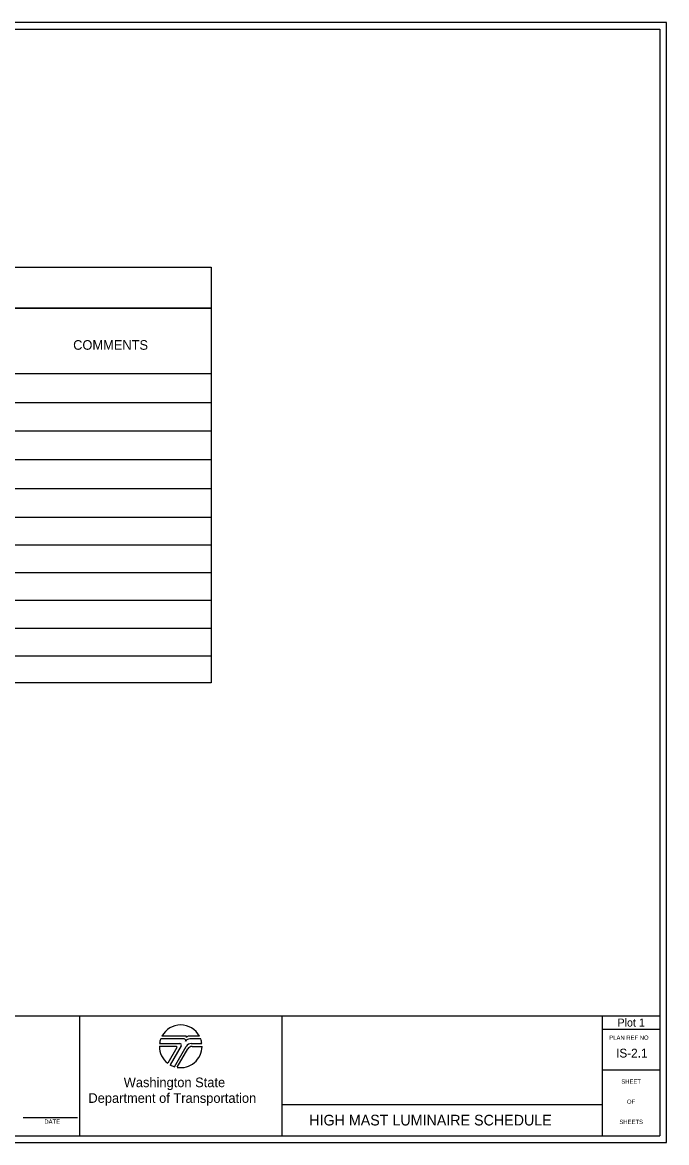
# Model space of a CAD drawing. Extents: x 99999.3 to 100015.8, y 99999.9 to 100010.4.
# Drawn here: x 100009.77 to 100015.81, y 99999.94 to 100010.44 of the extents above; entities that cross this region are included whole.
import ezdxf

# ---------------------------------------------------------------- set-up
doc = ezdxf.new("R2010")
doc.units = 0
for name, color, linetype in [('Level 20', 7, 'Continuous'), ('Level 40', 7, 'Continuous'), ('SH_GI_PlotLimits', 7, 'Continuous'), ('SH_GI_SheetBorder', 7, 'Continuous'), ('SH_GI_SheetLocationText', 7, 'Continuous'), ('SH_GI_SheetTextInCells', 7, 'Continuous'), ('SH_GI_WSDOTLogo', 7, 'Continuous')]:
    doc.layers.add(name, color=color, linetype=linetype)

msp = doc.modelspace()

# ---------------------------------------------------------------- linework, layer by layer
at = {"layer": 'Level 40'}
for p, q in [((100004.075, 100007.145), (100011.542, 100007.145)), ((100004.075, 100006.876), (100011.542, 100006.876)), ((100004.075, 100006.608), (100011.542, 100006.608)), ((100004.075, 100006.339), (100011.542, 100006.339)), ((100004.075, 100006.07), (100011.542, 100006.07)), ((100004.075, 100005.801), (100011.542, 100005.801)), ((100004.075, 100005.541), (100011.542, 100005.541)), ((100004.075, 100005.281), (100011.542, 100005.281)), ((100004.075, 100005.021), (100011.542, 100005.021)), ((100004.075, 100004.761), (100011.542, 100004.761)), ((100004.075, 100004.501), (100011.542, 100004.501))]:
    msp.add_line(p, q, dxfattribs=at)
for points in [[(100004.075, 100008.144), (100011.542, 100008.144), (100011.542, 100007.76), (100004.075, 100007.76)], [(100004.075, 100007.76), (100011.542, 100007.76), (100011.542, 100004.247), (100004.075, 100004.247)]]:
    msp.add_lwpolyline(points, close=True, dxfattribs=at)
at = {"layer": 'SH_GI_PlotLimits'}
msp.add_lwpolyline([(99999.312, 99999.937), (100015.812, 99999.937), (100015.812, 100010.437), (99999.312, 100010.437)], close=True, dxfattribs=at)
at = {"layer": 'SH_GI_SheetBorder'}
for p, q in [((100000, 100010.375), (100015.75, 100010.375)), ((100015.75, 100010.375), (100015.75, 100000)), ((100000, 100001.126), (100015.75, 100001.126)), ((100010.309, 100001.126), (100010.309, 100000)), ((100012.205, 100001.126), (100012.205, 100000)), ((100015.208, 100001.126), (100015.208, 100000)), ((100015.208, 100001.001), (100015.75, 100001.001)), ((100015.208, 100000.618), (100015.75, 100000.618)), ((100012.205, 100000.295), (100015.208, 100000.295)), ((100009.78, 100000.173), (100010.291, 100000.173)), ((100000, 100000), (100015.75, 100000))]:
    msp.add_line(p, q, dxfattribs=at)
at = {"layer": 'SH_GI_WSDOTLogo'}
for p, q in [((100011.059, 100000.866), (100011.25, 100000.866)), ((100011.289, 100000.909), (100011.07, 100000.909)), ((100011.303, 100000.935), (100011.081, 100000.935)), ((100011.261, 100000.846), (100011.157, 100000.667)), ((100011.433, 100000.935), (100011.335, 100000.935)), ((100011.445, 100000.909), (100011.343, 100000.909)), ((100011.343, 100000.909), (100011.343, 100000.909)), ((100011.356, 100000.866), (100011.456, 100000.866)), ((100011.057, 100000.84), (100011.215, 100000.84)), ((100011.222, 100000.828), (100011.136, 100000.681)), ((100011.199, 100000.649), (100011.309, 100000.839)), ((100011.224, 100000.643), (100011.324, 100000.816)), ((100011.365, 100000.839), (100011.457, 100000.839))]:
    msp.add_line(p, q, dxfattribs=at)
for centre, radius, start, end in [((100011.257, 100000.84), 0.2, 28.4787, 151.532), ((100011.257, 100000.84), 0.2, 159.696, 172.5057), ((100011.25, 100000.853), 0.0131, 329.7683, 90), ((100011.289, 100000.895), 0.0148, 327.8418, 89.9985), ((100011.343, 100000.861), 0.0484, 89.9953, 147.8238), ((100011.303, 100000.926), 0.00903, 329.8742, 90.0033), ((100011.356, 100000.812), 0.0542, 90, 149.9974), ((100011.335, 100000.907), 0.0287, 90.0072, 148.1676), ((100011.257, 100000.84), 0.2, 7.4943, 20.2941), ((100011.257, 100000.84), 0.2, 179.9986, 232.8433), ((100011.215, 100000.832), 0.0082, 329.7436, 90), ((100011.257, 100000.84), 0.2, 260.5455, 359.8086), ((100011.365, 100000.792), 0.0476, 90, 150.0543), ((100011.257, 100000.84), 0.2, 239.7929, 253.0448)]:
    msp.add_arc(centre, radius, start, end, dxfattribs=at)

# ---------------------------------------------------------------- texts
at = {"layer": 'Level 20'}
for s, height, p in [('COMMENTS', 0.09, (100010.249, 100007.369)), ('IS-2.1', 0.0825, (100015.339, 100000.735)), ('HIGH MAST LUMINAIRE SCHEDULE', 0.1, (100012.462, 100000.098))]:
    msp.add_text(s, height=height, dxfattribs=at).set_placement(p)
at = {"layer": 'SH_GI_SheetBorder'}
msp.add_text('PLAN REF NO', height=0.04003, dxfattribs=at).set_placement((100015.275, 100000.901))
at = {"layer": 'SH_GI_SheetLocationText'}
msp.add_text('Plot 1', height=0.075, dxfattribs=at).set_placement((100015.352, 100001.025))
at = {"layer": 'SH_GI_SheetTextInCells'}
for s, height, p in [('Washington State', 0.09007, (100010.723, 100000.457)), ('SHEET', 0.04, (100015.388, 100000.49)), ('Department of Transportation', 0.09007, (100010.392, 100000.31)), ('OF', 0.04, (100015.441, 100000.301)), ('DATE', 0.04, (100009.979, 100000.114)), ('SHEETS', 0.04, (100015.37, 100000.112))]:
    msp.add_text(s, height=height, dxfattribs=at).set_placement(p)

doc.saveas('drawing.dxf')
